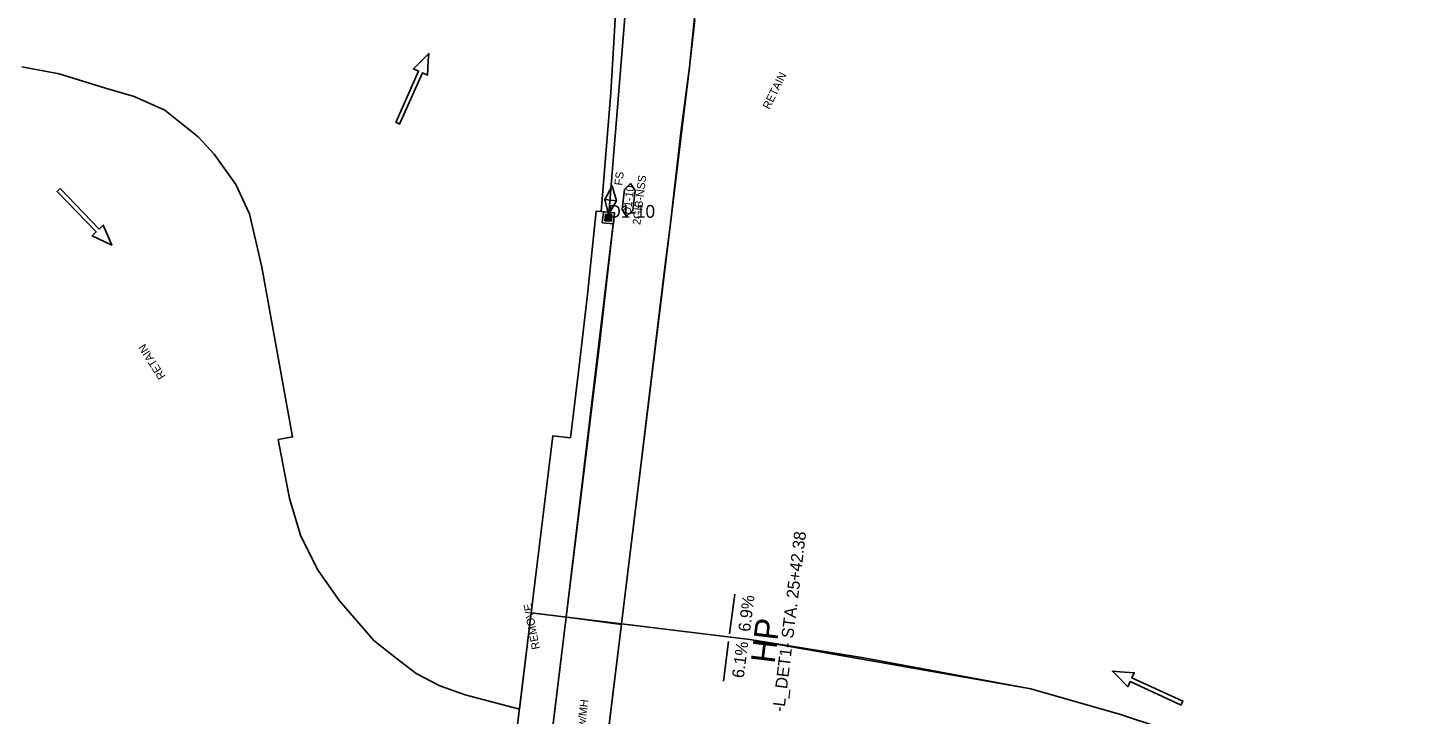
# Model space of a CAD drawing. Extents: x 465700 to 483515, y 488970 to 507540.
# Drawn here: x 480987 to 481856, y 490776 to 491205 of the extents above; entities that cross this region are included whole.
import ezdxf

# ---------------------------------------------------------------- set-up
doc = ezdxf.new("R2010")
doc.units = 0
for name, color, linetype in [('Default', 7, 'Continuous'), ('Exist Plan Preparation Drainage Flow Arrows', 7, 'Continuous'), ('Exist Plan Preparation Watershed Blue', 7, 'Continuous'), ('Prop Drainage Structure Box Number Symbol CELL', 7, 'Continuous'), ('Prop Drainage Structure Drop Inlet Grate 2 Narrow Slots and Sag Grates 840 24 CELL', 7, 'Continuous'), ('Prop Drainage Structure Drop Inlet Grate 2 Narrow Slots and Sag Grates 840 24 Label', 7, 'Continuous'), ('Prop Drainage Structure Junction Box with Manhole TB Label', 7, 'Continuous'), ('Prop Drainage Structure Pipe Collar Label', 7, 'Continuous'), ('Prop Drainage Structure Pipe RCP 15in Class III', 7, 'Continuous'), ('Prop Drainage Structure Plot Symbol 20 Scale CELL', 7, 'Continuous'), ('Prop Drainage Structure Plot Symbol 50 Scale CELL', 7, 'Continuous'), ('Prop Earthen Structure False Sump CELL', 7, 'Continuous'), ('Prop Earthen Structure False Sump Label', 7, 'Continuous'), ('Prop Plan Preparation Crest', 7, 'Continuous'), ('Prop Plan Preparation Crest Label', 7, 'Continuous'), ('Scratch_Level_8', 7, 'Continuous')]:
    doc.layers.add(name, color=color, linetype=linetype)

# ---------------------------------------------------------------- blocks, each defined once
blk = doc.blocks.new('Existing ground flow arrow')
at = {"layer": 'Default'}
blk.add_line((2.5, -4.33), (2.5, -4.33), dxfattribs=at)
blk.add_lwpolyline([(-1.29, -47.2), (-1.28, -12.53), (-4.77, -12.53), (-1.65, -4.33), (0, 0), (1.65, -4.33), (4.78, -12.53), (1.28, -12.52), (1.29, -47.19), (0, -47.2)], close=True, dxfattribs=at)

msp = doc.modelspace()

# ---------------------------------------------------------------- linework, layer by layer
at = {"layer": 'Exist Plan Preparation Watershed Blue'}
for points in [[(481409.74, 491273.14), (481400.35, 491179.93), (481388.23, 491080.67), (481357.88, 490832.14), (481323.3, 490836.37), (481344.18, 491006.64), (481353.57, 491089.04), (481345.2, 491089.83), (481351.25, 491164.11), (481355.63, 491237.92)], [(481403.82, 491209.49), (481400.35, 491179.93), (481395.3, 491140.87), (481388.23, 491080.67), (481385.29, 491056.6), (481369.55, 490927.72), (481357.88, 490832.14), (481438.14, 490822.33), (481507.98, 490811.09), (481613.6, 490791.65), (481669.68, 490775.55), (481742.88, 490751.39), (481842.61, 490718.46), (481938.49, 490800.19)], [(481669.68, 490775.55), (481613.6, 490791.65), (481438.14, 490822.33), (481301.55, 490839.02), (481294.11, 490778.84), (481260.32, 490787.86), (481244.4, 490793.34), (481229.54, 490801.15), (481217.1, 490810.65), (481203.26, 490821.84), (481181.78, 490846.5), (481168.5, 490865.53), (481157.55, 490886.97), (481150.54, 490910.54), (481143.49, 490947.32), (481152.4, 490948.97), (481152.4, 490948.97), (481133.16, 491055.07), (481125.49, 491088.34), (481116.97, 491106.64), (481103.42, 491125.55), (481093.37, 491136.53), (481072.61, 491153.17), (481053.37, 491161.71), (481035.44, 491166.96), (481006.59, 491175.72), (480983.31, 491180.16)], [(481178.35, 489921.07), (481181.18, 489944.23), (481192.1, 489942.89), (481199.42, 490002.85), (481223.67, 490201.37), (481232.65, 490274.58), (481301.55, 490839.02), (481357.88, 490832.14), (481339.74, 490683.62), (481315.49, 490485.09), (481303.36, 490385.83), (481279.12, 490187.3), (481254.87, 489988.78), (481242.75, 489889.52)]]:
    msp.add_lwpolyline(points, dxfattribs=at)
for points in [[(481301.55, 490839.02), (481315.07, 490949.74), (481325.99, 490948.41), (481328.72, 490970.74), (481331.45, 490993.08), (481336.76, 491037.88), (481336.76, 491037.88), (481342.02, 491089.98), (481345.2, 491089.83), (481353.57, 491089.04), (481323.3, 490836.37)], [(481241.45, 490191.91), (481273.35, 490227.27), (481291.24, 490286.57), (481303.36, 490385.83), (481311.9, 490453.82), (481327.61, 490584.35), (481339.74, 490683.62), (481353.35, 490795.1), (481357.83, 490831.75), (481325.41, 490836.1), (481323.3, 490836.37), (481263.76, 490349.7), (481254.45, 490271.98), (481232.65, 490274.58), (481223.67, 490201.37)], [(481259, 490360.8), (481243.71, 490365.51), (481284.29, 490697.69), (481301.55, 490839.02), (481323.3, 490836.37), (481281, 490489.23), (481265.22, 490360.1)], [(481339.74, 490683.62), (481381.2, 490650.46), (481429.31, 490629.05), (481487.85, 490619.44), (481541.27, 490608.02), (481609.7, 490592.3), (481694.85, 490612.96), (481802.24, 490660.02), (481819.54, 490679.79), (481842.61, 490718.46), (481742.88, 490751.39), (481669.68, 490775.55), (481613.6, 490791.65), (481438.14, 490822.33), (481357.88, 490832.14), (481339.74, 490683.62)]]:
    msp.add_lwpolyline(points, close=True, dxfattribs=at)
at = {"layer": 'Prop Drainage Structure Box Number Symbol CELL'}
msp.add_lwpolyline([(481358.24, 491091.04), (481359.77, 491103.55), (481363.47, 491107.24), (481366.55, 491102.89), (481365.02, 491090.37), (481360.98, 491086.84), (481358.24, 491091.04)], dxfattribs=at)
at = {"layer": 'Prop Drainage Structure Drop Inlet Grate 2 Narrow Slots and Sag Grates 840 24 CELL'}
for p, q in [((481348.59, 491085.99), (481348.59, 491085.99)), ((481349.56, 491083.89), (481349.56, 491083.89)), ((481349.75, 491085.88), (481349.75, 491085.88)), ((481349.94, 491087.88), (481349.94, 491087.88)), ((481350.91, 491085.77), (481350.91, 491085.77))]:
    msp.add_line(p, q, dxfattribs=at)
for points in [[(481348.4, 491084), (481348.78, 491087.98), (481351.1, 491087.77), (481350.72, 491083.78), (481348.4, 491084)], [(481348.47, 491084.06), (481348.84, 491087.92), (481351.03, 491087.71), (481350.67, 491083.85), (481348.47, 491084.06)], [(481348.48, 491084.07), (481348.66, 491085.98), (481350.84, 491085.77), (481350.66, 491083.86), (481348.48, 491084.07)], [(481348.66, 491086), (481348.84, 491087.91), (481351.02, 491087.7), (481350.84, 491085.79), (481348.66, 491086)], [(481348.68, 491084.22), (481348.7, 491084.39), (481350.51, 491084.22), (481350.49, 491084.05), (481348.68, 491084.22)], [(481348.71, 491084.51), (481348.72, 491084.69), (481350.54, 491084.52), (481350.52, 491084.34), (481348.71, 491084.51)], [(481348.73, 491084.81), (481348.75, 491084.98), (481350.57, 491084.81), (481350.55, 491084.64), (481348.73, 491084.81)], [(481348.76, 491085.1), (481348.78, 491085.28), (481350.59, 491085.11), (481350.58, 491084.93), (481348.76, 491085.1)], [(481348.79, 491085.4), (481348.81, 491085.58), (481350.62, 491085.4), (481350.61, 491085.23), (481348.79, 491085.4)], [(481348.82, 491085.7), (481348.84, 491085.87), (481350.65, 491085.7), (481350.63, 491085.52), (481348.82, 491085.7)], [(481348.85, 491086.07), (481348.87, 491086.24), (481350.69, 491086.07), (481350.67, 491085.9), (481348.85, 491086.07)], [(481348.88, 491086.36), (481348.9, 491086.54), (481350.71, 491086.37), (481350.7, 491086.19), (481348.88, 491086.36)], [(481348.91, 491086.66), (481348.93, 491086.84), (481350.74, 491086.66), (481350.72, 491086.49), (481348.91, 491086.66)], [(481348.94, 491086.95), (481348.95, 491087.13), (481350.77, 491086.96), (481350.75, 491086.78), (481348.94, 491086.95)], [(481348.97, 491087.25), (481348.98, 491087.43), (481350.8, 491087.26), (481350.78, 491087.08), (481348.97, 491087.25)], [(481348.99, 491087.55), (481349.01, 491087.72), (481350.83, 491087.55), (481350.81, 491087.37), (481348.99, 491087.55)]]:
    msp.add_lwpolyline(points, dxfattribs=at)
at = {"layer": 'Prop Drainage Structure Pipe RCP 15in Class III'}
msp.add_line((481349.75, 491085.88), (481375.95, 491408.81), dxfattribs=at)
at = {"layer": 'Prop Drainage Structure Plot Symbol 20 Scale CELL'}
msp.add_lwpolyline([(481347.57, 491084.08), (481347.95, 491088.06), (481351.93, 491087.69), (481351.55, 491083.7)], close=True, dxfattribs=at)
at = {"layer": 'Prop Drainage Structure Plot Symbol 50 Scale CELL'}
msp.add_lwpolyline([(481345.94, 491082.73), (481346.6, 491089.7), (481353.57, 491089.04), (481352.91, 491082.07)], close=True, dxfattribs=at)
at = {"layer": 'Prop Earthen Structure False Sump CELL'}
msp.add_lwpolyline([(481349.86, 491087.99), (481347.46, 491097.4), (481352.19, 491105.76), (481354.78, 491096.51), (481347.46, 491097.4), (481354.78, 491096.51), (481349.86, 491087.99)], dxfattribs=at)
at = {"layer": 'Prop Plan Preparation Crest'}
msp.add_line((481301.55, 490839.02), (481438.14, 490822.33), dxfattribs=at)
at = {"layer": 'Prop Plan Preparation Crest Label'}
for p, q in [((481428.7, 490850.8), (481425.49, 490826.01)), ((481421.63, 490796.26), (481424.84, 490821.05))]:
    msp.add_line(p, q, dxfattribs=at)
at = {"layer": 'Scratch_Level_8'}
msp.add_line((481349.75, 491085.88), (481375.95, 491408.81), dxfattribs=at)

# ---------------------------------------------------------------- block references
at = {"layer": 'Exist Plan Preparation Drainage Flow Arrows', "yscale": 1.0124070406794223}
for p, xscale, rotation in [((481237.46, 491188.6), 1.0124070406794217, -23.882435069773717), ((481039.47, 491068.84), 1.0124070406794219, -135.98659115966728), ((481664.69, 490802.57), 1.0124070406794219, 65.3167617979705)]:
    msp.add_blockref('Existing ground flow arrow', p, dxfattribs=dict(at, xscale=xscale, rotation=rotation))

# ---------------------------------------------------------------- texts
at = {"layer": 'Prop Drainage Structure Box Number Symbol CELL'}
msp.add_text('D1-10', height=5, rotation=83.03939, dxfattribs=at).set_placement((481363.76, 491087.61))
at = {"layer": 'Prop Drainage Structure Drop Inlet Grate 2 Narrow Slots and Sag Grates 840 24 Label'}
msp.add_text('2GIB-NSS', height=5, rotation=83.04227, dxfattribs=at).set_placement((481369.68, 491081.24))
at = {"layer": 'Prop Drainage Structure Junction Box with Manhole TB Label'}
msp.add_text('TB JB w/MH', height=5, rotation=83.04227, dxfattribs=at).set_placement((481332.74, 490747.77))
at = {"layer": 'Prop Drainage Structure Pipe Collar Label'}
for s, rotation, p in [('RETAIN', 63.76971, (481450.35, 491153.26)), ('RETAIN', 122.53493, (481073.23, 490986.85)), ('REMOVE', 100.64692, (481306.97, 490816.68))]:
    msp.add_text(s, height=5, rotation=rotation, dxfattribs=at).set_placement(p)
at = {"layer": 'Prop Earthen Structure False Sump Label'}
msp.add_text('FS', height=5, rotation=83.04227, dxfattribs=at).set_placement((481358.38, 491105.85))
at = {"layer": 'Prop Plan Preparation Crest Label'}
for s, height, rotation, p in [('-L_DET1- STA. 25+42.38', 7.5, 83.03651, (481459.59, 490776.88)), ('6.9%', 7.5, 82.60975, (481438.2, 490826.95)), ('HP', 15, 83.03986, (481453.58, 490807)), ('6.1%', 7.5, 82.60975, (481434.29, 490797.96))]:
    msp.add_text(s, height=height, rotation=rotation, dxfattribs=at).set_placement(p)
at = {"layer": 'Scratch_Level_8'}
msp.add_text('D1-10', height=8, dxfattribs=at).set_placement((481349.75, 491085.88))

doc.saveas('drawing.dxf')
